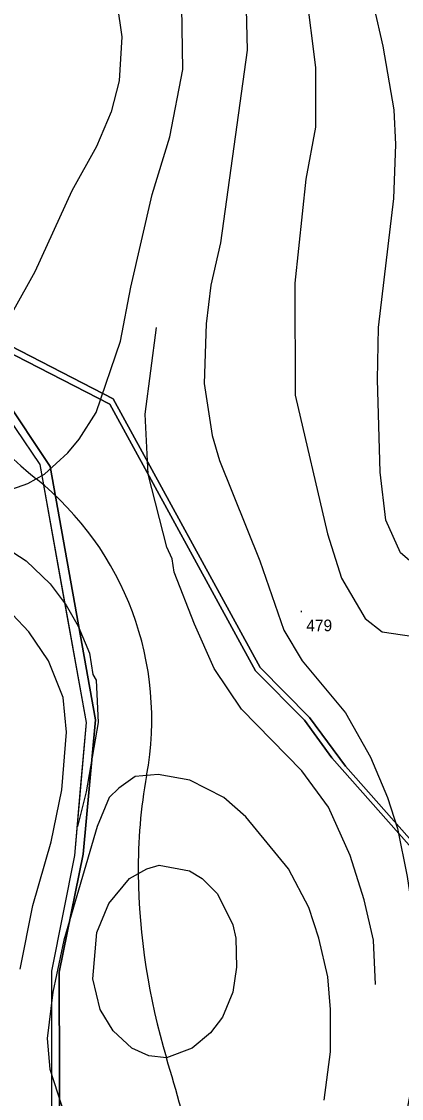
# Model space of a CAD drawing. Extents: x -510989 to -501240, y -1184665 to -1176098.
# Drawn here: x -510441 to -510244, y -1178532 to -1177973 of the extents above; entities that cross this region are included whole.
import ezdxf

# ---------------------------------------------------------------- set-up
doc = ezdxf.new("R2010")
doc.units = 0
for name, color, linetype in [('lesni_pozemek', 7, 'Continuous'), ('NAVRH_rozvodnice', 7, 'Continuous'), ('ostatni_plocha_x_ostatni_komunikace', 7, 'Continuous'), ('popis', 7, 'Continuous'), ('STAV_povodi', 7, 'Continuous'), ('vrstevnice_01', 7, 'Continuous'), ('vrstevnice_02', 7, 'Continuous'), ('vrstevnice_03', 7, 'Continuous'), ('vrstevnice_05', 7, 'Continuous')]:
    doc.layers.add(name, color=color, linetype=linetype)

msp = doc.modelspace()

# ---------------------------------------------------------------- linework, layer by layer
at = {"layer": 'lesni_pozemek'}
for points in [[(-510150.33, -1178540.25), (-510166.93, -1178518.96), (-510183.56, -1178490.36), (-510192.73, -1178464.93), (-510210.34, -1178439.16), (-510227.33, -1178410.72), (-510272.59, -1178359.57), (-510291.21, -1178334.45), (-510316.89, -1178308.41), (-510393.2, -1178168.97), (-510478.78, -1178124.83)], [(-510420.88, -1178577.47), (-510421.14, -1178466.58), (-510408.67, -1178405.28), (-510402.34, -1178335.6), (-510425.86, -1178204.15), (-510474.81, -1178130.78), (-510394.9, -1178171.72), (-510319.23, -1178310.15), (-510293.76, -1178335.76), (-510279.73, -1178355.25), (-510230.12, -1178411.23), (-510213.06, -1178439.47), (-510196.07, -1178464.34), (-510186.96, -1178488.21), (-510167.62, -1178523.59), (-510152.41, -1178542.1)]]:
    msp.add_lwpolyline(points, dxfattribs=at)
at = {"layer": 'NAVRH_rozvodnice'}
for centre, radius, start, end in [((-510303.17, -1178048.37), 207.74, 208.3463, 231.304), ((-510533.08, -1178335.38), 160, 349.5123, 51.304), ((-510118.77, -1178412.07), 261.34, 169.5123, 180.7519), ((-510030.27, -1178410.91), 349.86, 180.7519, 196.624), ((-511971.15, -1178990.4), 1675.69, 12.87549, 16.62404)]:
    msp.add_arc(centre, radius, start, end, dxfattribs=at)
at = {"layer": 'ostatni_plocha_x_ostatni_komunikace'}
for points in [[(-510441, -1179151), (-510432, -1179041), (-510433, -1179020), (-510429, -1178989), (-510426, -1178956), (-510412, -1178922), (-510407, -1178903), (-510402, -1178885), (-510400, -1178857), (-510399, -1178813), (-510391, -1178796), (-510388.94, -1178787.75), (-510387, -1178780), (-510388, -1178760), (-510384, -1178734), (-510425, -1178577), (-510425, -1178466), (-510413, -1178406), (-510407, -1178337), (-510431, -1178203), (-510507, -1178091), (-510517, -1178037), (-510522, -1177979), (-510527, -1177923)], [(-510478.78, -1178124.83), (-510393.2, -1178168.97), (-510316.89, -1178308.41), (-510291.21, -1178334.45), (-510272.59, -1178359.57), (-510227.33, -1178410.72), (-510210.34, -1178439.16), (-510192.73, -1178464.93), (-510183.56, -1178490.36), (-510166.93, -1178518.96), (-510150.33, -1178540.25)], [(-510474.81, -1178130.78), (-510425.86, -1178204.15), (-510402.34, -1178335.6), (-510408.67, -1178405.28), (-510421.14, -1178466.58), (-510420.88, -1178577.47)], [(-510152.41, -1178542.1), (-510167.62, -1178523.59), (-510186.96, -1178488.21), (-510196.07, -1178464.34), (-510213.06, -1178439.47), (-510230.12, -1178411.23), (-510279.73, -1178355.25), (-510293.76, -1178335.76), (-510319.23, -1178310.15), (-510394.9, -1178171.72), (-510474.81, -1178130.78)]]:
    msp.add_lwpolyline(points, dxfattribs=at)
at = {"layer": 'popis'}
msp.add_lwpolyline([(-510425, -1178577), (-510425, -1178521.5), (-510425, -1178466), (-510413, -1178406), (-510410, -1178371.5), (-510407, -1178337), (-510419, -1178270), (-510431, -1178203), (-510469, -1178147)], dxfattribs=at)
at = {"layer": 'STAV_povodi'}
for centre, radius, start, end in [((-510303.17, -1178048.37), 207.74, 208.3463, 231.304), ((-510533.08, -1178335.38), 160, 349.5123, 51.304), ((-510118.77, -1178412.07), 261.34, 169.5123, 180.7519), ((-510030.27, -1178410.91), 349.86, 180.7519, 196.624), ((-511971.15, -1178990.4), 1675.69, 12.87549, 16.62404)]:
    msp.add_arc(centre, radius, start, end, dxfattribs=at)
at = {"layer": 'vrstevnice_01'}
for points in [[(-510402.5, -1177885), (-510388.69, -1177981), (-510390.09, -1178004), (-510394.19, -1178020), (-510401.69, -1178038), (-510414.5, -1178061), (-510433.69, -1178103), (-510444.91, -1178123), (-510449.69, -1178128), (-510460.81, -1178137), (-510467.19, -1178141), (-510486, -1178147), (-510498.19, -1178147), (-510511.41, -1178143), (-510527.41, -1178134), (-510543.41, -1178119), (-510553.09, -1178103), (-510558.59, -1178091), (-510567.09, -1178064), (-510581.91, -1177990), (-510587.31, -1177971)], [(-510325.5, -1177910), (-510323.5, -1177988), (-510337.41, -1178088), (-510342.41, -1178110), (-510344.91, -1178130), (-510345.91, -1178161), (-510341.81, -1178188), (-510338, -1178201), (-510317.09, -1178253), (-510304.5, -1178289), (-510295.09, -1178305), (-510272.59, -1178332), (-510259.59, -1178355), (-510250.81, -1178376), (-510245.59, -1178392), (-510240.5, -1178417), (-510235.09, -1178454), (-510233.81, -1178479), (-510237, -1178518), (-510241.91, -1178545)], [(-510149, -1178541), (-510146.69, -1178503), (-510151.81, -1178450), (-510152.69, -1178402), (-510156.81, -1178370), (-510166.91, -1178336), (-510182.81, -1178302), (-510194.59, -1178268), (-510199.19, -1178262), (-510208, -1178257), (-510214, -1178256), (-510230.59, -1178257), (-510238.19, -1178254), (-510244.09, -1178249), (-510251.59, -1178232), (-510254.5, -1178207), (-510255.91, -1178159), (-510255.41, -1178132), (-510247.41, -1178065), (-510246.41, -1178037), (-510247.31, -1178019), (-510253.09, -1177986), (-510262.41, -1177945)], [(-510441.41, -1178465), (-510434.81, -1178432), (-510425.31, -1178399), (-510419.81, -1178372), (-510417.31, -1178342), (-510419.09, -1178324), (-510426.69, -1178305), (-510436.81, -1178290), (-510454.09, -1178272)], [(-510353.59, -1178414), (-510347, -1178418), (-510339, -1178426), (-510331, -1178442), (-510329.41, -1178449), (-510329.19, -1178464), (-510331, -1178477), (-510336.41, -1178490), (-510342.59, -1178498), (-510352.19, -1178506), (-510365.5, -1178511), (-510374.59, -1178510), (-510383.41, -1178506), (-510393.09, -1178497), (-510399.81, -1178486), (-510403.59, -1178470), (-510401.59, -1178446), (-510395.31, -1178431), (-510384.59, -1178418), (-510375.59, -1178413), (-510369.31, -1178411), (-510353.59, -1178414)]]:
    msp.add_lwpolyline(points, dxfattribs=at)
at = {"layer": 'vrstevnice_02'}
for points in [[(-510410.81, -1178190), (-510401.91, -1178176), (-510389.31, -1178139), (-510384, -1178111), (-510372.91, -1178063), (-510363.69, -1178033), (-510357, -1177998), (-510358.09, -1177933)], [(-510293.09, -1177957), (-510288.09, -1177997), (-510288.19, -1178028), (-510293.09, -1178055), (-510298.91, -1178109), (-510298.69, -1178167), (-510281.91, -1178239), (-510274.69, -1178262), (-510262.41, -1178283), (-510253.59, -1178290), (-510232.41, -1178293), (-510224.31, -1178299), (-510221.31, -1178302), (-510214.19, -1178316), (-510198, -1178376), (-510192.81, -1178408), (-510189.81, -1178442), (-510189.59, -1178476), (-510191.5, -1178517), (-510196.09, -1178546)], [(-510618.41, -1177967), (-510608.69, -1177988), (-510604.81, -1177999), (-510598.19, -1178036), (-510596.09, -1178088), (-510593.91, -1178114), (-510588.59, -1178135), (-510581.81, -1178151), (-510564.69, -1178174), (-510556.31, -1178182), (-510535.5, -1178196), (-510519.09, -1178204), (-510477.19, -1178219), (-510468.91, -1178221), (-510457.69, -1178220), (-510437.41, -1178213), (-510428.69, -1178208), (-510416.69, -1178197), (-510410.81, -1178190)], [(-510283.69, -1178533), (-510280.31, -1178508), (-510280.41, -1178486), (-510281.81, -1178469), (-510286.31, -1178449), (-510291.59, -1178433), (-510302.19, -1178413), (-510324.19, -1178386), (-510335.69, -1178376), (-510353.31, -1178367), (-510369.81, -1178364), (-510381.69, -1178365), (-510390.19, -1178371), (-510395.19, -1178376), (-510401.41, -1178391), (-510418.69, -1178450), (-510424.5, -1178477), (-510427.31, -1178501), (-510425.91, -1178517), (-510417.81, -1178542)]]:
    msp.add_lwpolyline(points, dxfattribs=at)
at = {"layer": 'vrstevnice_03'}
for points in [[(-510256.91, -1178473), (-510258.09, -1178450), (-510262.81, -1178429), (-510270.09, -1178406), (-510281.41, -1178381), (-510295.19, -1178362), (-510326.5, -1178330), (-510340.69, -1178309), (-510351, -1178286), (-510361.5, -1178259), (-510362.5, -1178252), (-510365.31, -1178246), (-510374.91, -1178208), (-510376.5, -1178177), (-510370.59, -1178132)], [(-510481.69, -1178234), (-510463.81, -1178239), (-510452.31, -1178244), (-510438.31, -1178253), (-510425.81, -1178265), (-510417.5, -1178276), (-510411.31, -1178287), (-510405.41, -1178301), (-510403.59, -1178312), (-510401.91, -1178315), (-510400.91, -1178337), (-510407.09, -1178373), (-510411.59, -1178391)]]:
    msp.add_lwpolyline(points, dxfattribs=at)

# ---------------------------------------------------------------- texts
at = {"layer": 'vrstevnice_05'}
for s, p in [('.', (-510296.59, -1178279.82)), ('479', (-510292.88, -1178289.58))]:
    msp.add_text(s, height=6, dxfattribs=at).set_placement(p)

doc.saveas('drawing.dxf')
